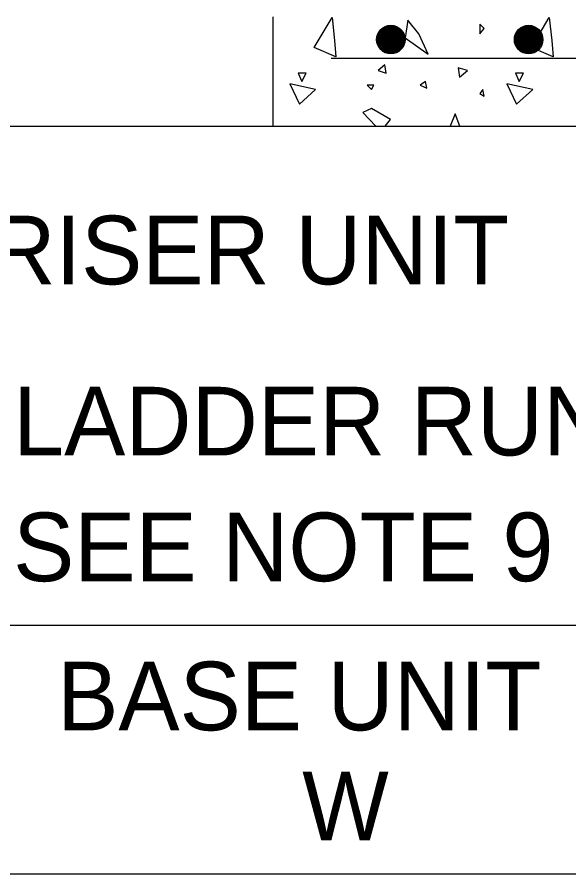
# Model space of a CAD drawing. Extents: x 5.8 to 18, y -5.2 to 5.4.
# Drawn here: x 11.78 to 12.262, y -1.468 to -0.719 of the extents above; entities that cross this region are included whole.
import ezdxf

# ---------------------------------------------------------------- set-up
doc = ezdxf.new("R2010")
doc.units = 0
for name, color, linetype in [('DETL-DIMS', 7, 'Continuous'), ('DETL-LINE', 7, 'Continuous'), ('DETL-NOTE', 7, 'Continuous'), ('DETL-PATT', 7, 'Continuous')]:
    doc.layers.add(name, color=color, linetype=linetype)

msp = doc.modelspace()

# ---------------------------------------------------------------- linework, layer by layer
at = {"layer": 'DETL-DIMS'}
msp.add_line((11.5809, -1.46798), (12.51612, -1.46798), dxfattribs=at)
at = {"layer": 'DETL-LINE'}
for p, q in [((12.00361, -0.81414), (12.00361, -0.71873)), ((12.05439, -0.75473), (12.56941, -0.75473)), ((11.5231, -0.81414), (12.56114, -0.81414)), ((11.53796, -1.25045), (12.55761, -1.25045))]:
    msp.add_line(p, q, dxfattribs=at)
for centre, radius in [((12.10652, -0.73854), 0.01247), ((12.22703, -0.73854), 0.01247), ((12.10641, -0.73843), 0.01163), ((12.10529, -0.73843), 0.01009), ((12.10655, -0.73873), 0.01122), ((12.10688, -0.73926), 0.011), ((12.10682, -0.73886), 0.01024), ((12.10571, -0.73794), 0.00834), ((12.1071, -0.73892), 0.00969), ((12.10718, -0.7392), 0.00918), ((12.10551, -0.73892), 0.00724), ((12.10731, -0.73934), 0.00876), ((12.10718, -0.73955), 0.00835), ((12.10488, -0.73934), 0.00578), ((12.10739, -0.73955), 0.00814), ((12.10724, -0.73941), 0.00786), ((12.10759, -0.73961), 0.00751), ((12.10767, -0.73947), 0.00704), ((12.10773, -0.73939), 0.00655), ((12.10773, -0.73926), 0.006), ((12.1078, -0.73941), 0.00565), ((12.22692, -0.73843), 0.01163), ((12.2258, -0.73843), 0.01009), ((12.22706, -0.73873), 0.01122), ((12.22739, -0.73926), 0.011), ((12.22733, -0.73886), 0.01024), ((12.22622, -0.73794), 0.00834), ((12.22761, -0.73892), 0.00969), ((12.22769, -0.7392), 0.00918), ((12.22602, -0.73892), 0.00724), ((12.22782, -0.73934), 0.00876), ((12.22769, -0.73955), 0.00835), ((12.22539, -0.73934), 0.00578), ((12.2279, -0.73955), 0.00814), ((12.22775, -0.73941), 0.00786), ((12.2281, -0.73961), 0.00751), ((12.22818, -0.73947), 0.00704), ((12.22824, -0.73939), 0.00655), ((12.22824, -0.73926), 0.006), ((12.22831, -0.73941), 0.00565), ((12.10584, -0.73906), 0.00467), ((12.1078, -0.73947), 0.0051), ((12.10802, -0.7399), 0.00488), ((12.10814, -0.73996), 0.00445), ((12.10814, -0.73985), 0.0039), ((12.10829, -0.73975), 0.00377), ((12.10829, -0.7401), 0.00347), ((12.10843, -0.73983), 0.00333), ((12.10849, -0.7399), 0.00285), ((12.10829, -0.73969), 0.00238), ((12.10857, -0.73998), 0.00212), ((12.10865, -0.73996), 0.00175), ((12.10878, -0.74004), 0.00133), ((12.10878, -0.7399), 0.00118), ((12.1092, -0.73996), 0.00148), ((12.10876, -0.7399), 0.000769), ((12.10863, -0.7399), 0.000362), ((12.10892, -0.7399), 0.00023), ((12.22635, -0.73906), 0.00467), ((12.22831, -0.73947), 0.0051), ((12.22853, -0.7399), 0.00488), ((12.22865, -0.73996), 0.00445), ((12.22865, -0.73985), 0.0039), ((12.2288, -0.73975), 0.00377), ((12.2288, -0.7401), 0.00347), ((12.22894, -0.73983), 0.00333), ((12.229, -0.7399), 0.00285), ((12.2288, -0.73969), 0.00238), ((12.22908, -0.73998), 0.00212), ((12.22916, -0.73996), 0.00175), ((12.22929, -0.74004), 0.00133), ((12.22929, -0.7399), 0.00118), ((12.22971, -0.73996), 0.00148), ((12.22927, -0.7399), 0.000769), ((12.22914, -0.7399), 0.000362), ((12.22943, -0.7399), 0.00023)]:
    msp.add_circle(centre, radius, dxfattribs=at)
at = {"layer": 'DETL-PATT'}
for points in [[(12.05733, -0.73951), (12.05843, -0.75363), (12.03953, -0.74543), (12.05506, -0.71916)], [(12.12141, -0.72171), (12.11914, -0.73696), (12.13922, -0.75135), (12.13102, -0.73355)], [(12.18439, -0.72508), (12.18439, -0.73355), (12.18804, -0.72877)], [(12.24733, -0.73951), (12.24847, -0.75363), (12.22957, -0.74543), (12.2451, -0.71916)], [(12.10137, -0.76069), (12.09545, -0.76547), (12.10251, -0.76802)], [(12.16545, -0.7632), (12.16659, -0.77139), (12.17365, -0.76547)], [(12.02541, -0.76802), (12.02878, -0.77508), (12.03247, -0.76802)], [(12.21545, -0.76802), (12.21882, -0.77508), (12.22251, -0.76802)], [(12.01808, -0.77732), (12.02655, -0.79512), (12.04067, -0.78214)], [(12.08584, -0.77845), (12.08949, -0.78214), (12.09176, -0.77845)], [(12.13216, -0.77845), (12.13808, -0.781), (12.13694, -0.77508)], [(12.20808, -0.77732), (12.21655, -0.79512), (12.23067, -0.78214)], [(12.18439, -0.78579), (12.18804, -0.78806), (12.1869, -0.78214)]]:
    msp.add_lwpolyline(points, close=True, dxfattribs=at)
for points in [[(12.10153, -0.81414), (12.10616, -0.80837), (12.08949, -0.79881), (12.08216, -0.80218), (12.09329, -0.81414)], [(12.16698, -0.81414), (12.1629, -0.80359), (12.15827, -0.81414)]]:
    msp.add_lwpolyline(points, dxfattribs=at)

# ---------------------------------------------------------------- texts
at = {"layer": 'DETL-NOTE'}
for s, p in [('RISER UNIT', (11.75537, -0.95257)), ('LADDER RUNGS', (11.77612, -1.10214)), ('SEE NOTE 9', (11.77612, -1.21214)), ('BASE UNIT', (11.81471, -1.34249)), ('W', (12.02898, -1.43857))]:
    msp.add_text(s, height=0.06, dxfattribs=at).set_placement(p)

doc.saveas('drawing.dxf')
